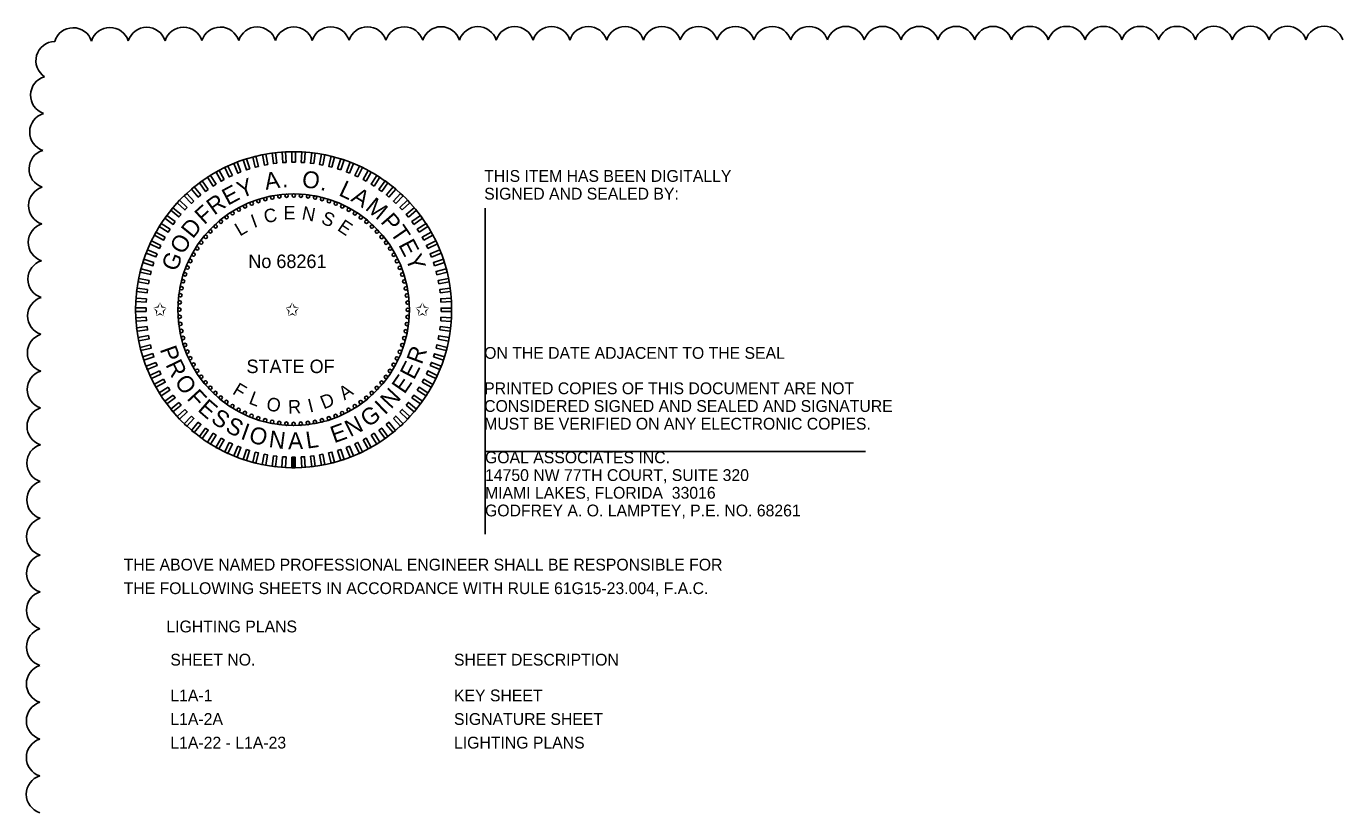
# Model space of a CAD drawing. Extents: x -811.2 to -795.1, y -2238.2 to -2204.
# Drawn here: x -811.08 to -803.27, y -2220.54 to -2215.88 of the extents above; entities that cross this region are included whole.
import ezdxf

# ---------------------------------------------------------------- set-up
doc = ezdxf.new("R2010")
doc.units = 0
for name, color, linetype in [('AdhocPoint_dp', 7, 'Continuous'), ('Cloud_dp', 7, 'Continuous'), ('PlotBorder_dp', 7, 'Continuous'), ('TextMinor', 7, 'Continuous'), ('TextMisc', 7, 'Continuous'), ('TextShtNo', 7, 'Continuous')]:
    doc.layers.add(name, color=color, linetype=linetype)

msp = doc.modelspace()

# ---------------------------------------------------------------- linework, layer by layer
at = {"layer": 'AdhocPoint_dp'}
for p, q in [((-808.3546, -2216.9552), (-808.3546, -2218.8899)), ((-808.3546, -2218.3999), (-806.0979, -2218.3999))]:
    msp.add_line(p, q, dxfattribs=at)
at = {"layer": 'Cloud_dp'}
for centre, radius, start, end in [((-810.7982, -2216.0002), 0.1145, 18.05658, 163.05658), ((-810.58, -2215.9986), 0.1145, 17.79982, 162.79982), ((-810.3617, -2215.9976), 0.1145, 17.71875, 162.71875), ((-810.1434, -2215.9968), 0.1145, 17.67426, 162.67426), ((-809.9251, -2215.9962), 0.1145, 17.64508, 162.64508), ((-809.7068, -2215.9957), 0.1145, 17.62402, 162.62402), ((-809.4885, -2215.9953), 0.1145, 17.60791, 162.60791), ((-809.2702, -2215.9949), 0.1145, 17.59506, 162.59506), ((-809.0518, -2215.9946), 0.1145, 17.5845, 162.5845), ((-808.8335, -2215.9943), 0.1145, 17.57563, 162.57563), ((-808.6152, -2215.994), 0.1145, 17.56803, 162.56803), ((-808.3969, -2215.9937), 0.1145, 17.56143, 162.56143), ((-808.1786, -2215.9935), 0.1145, 17.55563, 162.55563), ((-807.9602, -2215.9933), 0.1145, 17.55047, 162.55047), ((-807.7419, -2215.9931), 0.1145, 17.54585, 162.54585), ((-807.5236, -2215.993), 0.1145, 17.54168, 162.54168), ((-807.3053, -2215.9928), 0.1145, 17.53789, 162.53789), ((-807.087, -2215.9927), 0.1145, 17.53443, 162.53443), ((-806.8686, -2215.9925), 0.1145, 17.53125, 162.53125), ((-806.6503, -2215.9924), 0.1145, 17.52832, 162.52832), ((-806.432, -2215.9923), 0.1145, 17.52559, 162.52559), ((-806.2137, -2215.9922), 0.1145, 17.52306, 162.52306), ((-805.9953, -2215.9922), 0.1145, 17.5207, 162.5207), ((-805.777, -2215.9921), 0.1145, 17.51849, 162.51849), ((-805.5587, -2215.992), 0.1145, 17.51642, 162.51642), ((-805.3404, -2215.992), 0.1145, 17.51447, 162.51447), ((-805.1221, -2215.9919), 0.1145, 17.51263, 162.51263), ((-804.9037, -2215.9919), 0.1145, 17.51089, 162.51089), ((-804.6854, -2215.9918), 0.1145, 17.50924, 162.50924), ((-804.4671, -2215.9918), 0.1145, 17.50767, 162.50767), ((-804.2488, -2215.9918), 0.1145, 17.50619, 162.50619), ((-804.0304, -2215.9917), 0.1145, 17.50477, 162.50477), ((-803.8121, -2215.9917), 0.1145, 17.50342, 162.50342), ((-803.5938, -2215.9917), 0.1145, 17.50213, 162.50213), ((-803.3755, -2215.9917), 0.1145, 17.5009, 162.5009), ((-810.9047, -2216.0812), 0.1144, 91.47713, 236.47713), ((-810.9365, -2216.2866), 0.1145, 105.90805, 250.90805), ((-810.9416, -2216.5046), 0.1145, 106.41676, 251.41676), ((-810.9452, -2216.7227), 0.1145, 106.67623, 251.67623), ((-810.9481, -2216.9409), 0.1145, 106.84098, 251.84098), ((-810.9504, -2217.1592), 0.1145, 106.95758, 251.95758), ((-810.9523, -2217.3774), 0.1145, 107.04572, 252.04572), ((-810.9539, -2217.5957), 0.1145, 107.11538, 252.11538), ((-810.9552, -2217.814), 0.1145, 107.17224, 252.17224), ((-810.9564, -2218.0323), 0.1145, 107.21979, 252.21979), ((-810.9574, -2218.2506), 0.1145, 107.26033, 252.26033), ((-810.9582, -2218.4689), 0.1145, 107.29543, 252.29543), ((-810.9589, -2218.6872), 0.1145, 107.3262, 252.3262), ((-810.9595, -2218.9055), 0.1145, 107.35348, 252.35348), ((-810.9601, -2219.1238), 0.1145, 107.37786, 252.37786), ((-810.9605, -2219.3421), 0.1145, 107.39984, 252.39984), ((-810.9608, -2219.5604), 0.1145, 107.41978, 252.41978), ((-810.9611, -2219.7788), 0.1145, 107.43798, 252.43798), ((-810.9613, -2219.9971), 0.1145, 107.45468, 252.45468), ((-810.9614, -2220.2154), 0.1145, 107.47007, 252.47007), ((-810.9615, -2220.4337), 0.1145, 107.48432, 252.48432)]:
    msp.add_arc(centre, radius, start, end, dxfattribs=at)
at = {"layer": 'TextMinor'}
for radius in [0.9375, 0.6875]:
    msp.add_circle((-809.4901, -2217.5586), radius, dxfattribs=at)
at = {"layer": 'TextShtNo'}
for p, q in [((-809.5001, -2218.4961), (-809.5003, -2218.4336)), ((-809.4901, -2218.4961), (-809.4903, -2218.4336)), ((-809.4801, -2218.4961), (-809.4803, -2218.4336))]:
    msp.add_line(p, q, dxfattribs=at)
for points in [[(-809.8028, -2216.7413), (-809.8215, -2216.7487), (-809.8445, -2216.6906), (-809.8258, -2216.6832)], [(-809.7508, -2216.7232), (-809.77, -2216.7295), (-809.7893, -2216.6701), (-809.7701, -2216.6639)], [(-809.6979, -2216.7085), (-809.7174, -2216.7135), (-809.7329, -2216.6531), (-809.7134, -2216.648)], [(-809.6441, -2216.6971), (-809.6639, -2216.7009), (-809.6756, -2216.6396), (-809.6558, -2216.6358)], [(-809.5897, -2216.6892), (-809.6097, -2216.6917), (-809.6175, -2216.6298), (-809.5975, -2216.6272)], [(-809.5349, -2216.6846), (-809.555, -2216.6859), (-809.559, -2216.6236), (-809.5388, -2216.6223)], [(-809.4799, -2216.6836), (-809.5001, -2216.6836), (-809.5001, -2216.6211), (-809.4799, -2216.6211)], [(-809.425, -2216.6859), (-809.4452, -2216.6847), (-809.4412, -2216.6223), (-809.4211, -2216.6236)], [(-809.3703, -2216.6917), (-809.3904, -2216.6892), (-809.3825, -2216.6273), (-809.3625, -2216.6298)], [(-809.3162, -2216.701), (-809.336, -2216.6972), (-809.3243, -2216.6358), (-809.3045, -2216.6396)], [(-809.2626, -2216.7136), (-809.2822, -2216.7086), (-809.2667, -2216.6481), (-809.2471, -2216.6531)], [(-809.21, -2216.7295), (-809.2292, -2216.7233), (-809.2099, -2216.6639), (-809.1907, -2216.6701)], [(-809.1585, -2216.7488), (-809.1773, -2216.7413), (-809.1543, -2216.6833), (-809.1355, -2216.6907)], [(-809.9504, -2216.8143), (-809.9674, -2216.8251), (-810.0009, -2216.7724), (-809.9838, -2216.7616)], [(-809.9027, -2216.7869), (-809.9204, -2216.7966), (-809.9505, -2216.7419), (-809.9328, -2216.7322)], [(-809.8535, -2216.7625), (-809.8717, -2216.7711), (-809.8983, -2216.7146), (-809.8801, -2216.706)], [(-809.1083, -2216.7712), (-809.1266, -2216.7626), (-809.1, -2216.7061), (-809.0817, -2216.7147)], [(-809.0596, -2216.7967), (-809.0773, -2216.787), (-809.0473, -2216.7323), (-809.0296, -2216.742)], [(-809.0127, -2216.8252), (-809.0297, -2216.8144), (-808.9962, -2216.7617), (-808.9792, -2216.7725)], [(-810.04, -2216.8779), (-810.0556, -2216.8907), (-810.0954, -2216.8426), (-810.0798, -2216.8298)], [(-809.9962, -2216.8447), (-810.0125, -2216.8566), (-810.0492, -2216.806), (-810.0329, -2216.7942)], [(-808.9676, -2216.8567), (-808.9839, -2216.8448), (-808.9472, -2216.7943), (-808.9308, -2216.8061)], [(-808.9245, -2216.8909), (-808.9401, -2216.878), (-808.9003, -2216.8299), (-808.8847, -2216.8427)], [(-810.121, -2216.9522), (-810.1348, -2216.9669), (-810.1804, -2216.9241), (-810.1665, -2216.9094)], [(-810.0817, -2216.9137), (-810.0964, -2216.9276), (-810.1392, -2216.882), (-810.1244, -2216.8682)], [(-808.8837, -2216.9277), (-808.8984, -2216.9139), (-808.8557, -2216.8684), (-808.841, -2216.8822)], [(-808.8453, -2216.967), (-808.8591, -2216.9523), (-808.8136, -2216.9096), (-808.7998, -2216.9243)], [(-810.192, -2217.036), (-810.2039, -2217.0523), (-810.2544, -2217.0156), (-810.2426, -2216.9993)], [(-810.1579, -2216.993), (-810.1707, -2217.0085), (-810.2188, -2216.9687), (-810.206, -2216.9532)], [(-808.8094, -2217.0087), (-808.8223, -2216.9931), (-808.7742, -2216.9533), (-808.7613, -2216.9689)], [(-808.7762, -2217.0525), (-808.7881, -2217.0362), (-808.7376, -2216.9995), (-808.7257, -2217.0158)], [(-810.2235, -2217.0811), (-810.2343, -2217.0982), (-810.287, -2217.0647), (-810.2762, -2217.0477)], [(-808.7459, -2217.0983), (-808.7567, -2217.0813), (-808.7039, -2217.0478), (-808.6931, -2217.0649)], [(-810.2775, -2217.1768), (-810.2861, -2217.1951), (-810.3426, -2217.1685), (-810.334, -2217.1502)], [(-810.252, -2217.1281), (-810.2617, -2217.1458), (-810.3164, -2217.1157), (-810.3067, -2217.098)], [(-808.7184, -2217.146), (-808.7281, -2217.1283), (-808.6734, -2217.0982), (-808.6637, -2217.1159)], [(-808.694, -2217.1952), (-808.7026, -2217.177), (-808.6461, -2217.1504), (-808.6375, -2217.1686)], [(-810.3, -2217.227), (-810.3074, -2217.2458), (-810.3654, -2217.2228), (-810.358, -2217.204)], [(-808.6728, -2217.2459), (-808.6802, -2217.2272), (-808.6222, -2217.2042), (-808.6147, -2217.223)], [(-810.3351, -2217.3311), (-810.3401, -2217.3507), (-810.4006, -2217.3351), (-810.3956, -2217.3156)], [(-810.3192, -2217.2785), (-810.3254, -2217.2977), (-810.3848, -2217.2784), (-810.3786, -2217.2592)], [(-808.6548, -2217.2979), (-808.661, -2217.2787), (-808.6016, -2217.2594), (-808.5954, -2217.2786)], [(-808.64, -2217.3508), (-808.6451, -2217.3313), (-808.5846, -2217.3158), (-808.5796, -2217.3353)], [(-810.3477, -2217.3846), (-810.3515, -2217.4044), (-810.4129, -2217.3927), (-810.4091, -2217.3729)], [(-808.6287, -2217.4046), (-808.6325, -2217.3848), (-808.5711, -2217.3731), (-808.5673, -2217.3929)], [(-810.357, -2217.4388), (-810.3595, -2217.4588), (-810.4215, -2217.451), (-810.4189, -2217.431)], [(-808.6207, -2217.459), (-808.6232, -2217.439), (-808.5613, -2217.4312), (-808.5588, -2217.4512)], [(-810.3652, -2217.5484), (-810.3652, -2217.5686), (-810.4276, -2217.5686), (-810.4276, -2217.5484)], [(-810.3628, -2217.4935), (-810.3641, -2217.5136), (-810.4264, -2217.5097), (-810.4251, -2217.4896)], [(-808.6162, -2217.5138), (-808.6174, -2217.4937), (-808.5551, -2217.4897), (-808.5539, -2217.5099)], [(-808.6151, -2217.5688), (-808.6151, -2217.5486), (-808.5527, -2217.5486), (-808.5527, -2217.5688)], [(-810.3641, -2217.6034), (-810.3628, -2217.6235), (-810.4251, -2217.6274), (-810.4264, -2217.6073)], [(-808.6175, -2217.6237), (-808.6162, -2217.6036), (-808.5539, -2217.6075), (-808.5551, -2217.6276)], [(-810.3595, -2217.6582), (-810.357, -2217.6782), (-810.4189, -2217.686), (-810.4215, -2217.666)], [(-810.3516, -2217.7125), (-810.3478, -2217.7324), (-810.4091, -2217.7441), (-810.4129, -2217.7242)], [(-808.6233, -2217.6784), (-808.6207, -2217.6583), (-808.5588, -2217.6662), (-808.5613, -2217.6862)], [(-810.3402, -2217.7663), (-810.3352, -2217.7859), (-810.3957, -2217.8014), (-810.4007, -2217.7819)], [(-808.6451, -2217.7861), (-808.6401, -2217.7665), (-808.5796, -2217.782), (-808.5846, -2217.8016)], [(-808.6325, -2217.7326), (-808.6287, -2217.7127), (-808.5674, -2217.7244), (-808.5712, -2217.7443)], [(-810.3255, -2217.8193), (-810.3192, -2217.8385), (-810.3786, -2217.8578), (-810.3849, -2217.8386)], [(-808.6611, -2217.8387), (-808.6548, -2217.8195), (-808.5954, -2217.8388), (-808.6017, -2217.858)], [(-810.3075, -2217.8712), (-810.3, -2217.89), (-810.3581, -2217.913), (-810.3655, -2217.8942)], [(-810.2862, -2217.9219), (-810.2776, -2217.9402), (-810.3341, -2217.9668), (-810.3427, -2217.9485)], [(-808.7027, -2217.9404), (-808.6941, -2217.9221), (-808.6376, -2217.9487), (-808.6462, -2217.967)], [(-808.6803, -2217.8902), (-808.6729, -2217.8714), (-808.6148, -2217.8944), (-808.6222, -2217.9132)], [(-810.2618, -2217.9712), (-810.2521, -2217.9889), (-810.3068, -2218.019), (-810.3165, -2218.0013)], [(-810.2344, -2218.0189), (-810.2236, -2218.0359), (-810.2763, -2218.0694), (-810.2871, -2218.0523)], [(-808.7568, -2218.0361), (-808.746, -2218.019), (-808.6932, -2218.0525), (-808.704, -2218.0695)], [(-808.7282, -2217.9891), (-808.7185, -2217.9714), (-808.6638, -2218.0015), (-808.6735, -2218.0191)], [(-810.204, -2218.0647), (-810.1922, -2218.081), (-810.2427, -2218.1177), (-810.2545, -2218.1014)], [(-808.7882, -2218.0812), (-808.7763, -2218.0648), (-808.7258, -2218.1015), (-808.7377, -2218.1179)], [(-810.1708, -2218.1085), (-810.158, -2218.1241), (-810.2061, -2218.1639), (-810.2189, -2218.1483)], [(-810.135, -2218.1502), (-810.1211, -2218.1649), (-810.1667, -2218.2076), (-810.1805, -2218.1929)], [(-808.8592, -2218.165), (-808.8454, -2218.1503), (-808.7999, -2218.193), (-808.8137, -2218.2078)], [(-808.8224, -2218.1242), (-808.8095, -2218.1086), (-808.7614, -2218.1484), (-808.7743, -2218.164)], [(-810.0965, -2218.1895), (-810.0818, -2218.2033), (-810.1246, -2218.2488), (-810.1393, -2218.235)], [(-810.0557, -2218.2263), (-810.0402, -2218.2392), (-810.08, -2218.2873), (-810.0955, -2218.2744)], [(-808.9402, -2218.2393), (-808.9247, -2218.2264), (-808.8848, -2218.2745), (-808.9004, -2218.2874)], [(-808.8985, -2218.2034), (-808.8838, -2218.1896), (-808.8411, -2218.2351), (-808.8558, -2218.2489)], [(-810.0127, -2218.2605), (-809.9964, -2218.2724), (-810.0331, -2218.3229), (-810.0494, -2218.311)], [(-809.9676, -2218.2919), (-809.9505, -2218.3028), (-809.984, -2218.3555), (-810.001, -2218.3447)], [(-809.9206, -2218.3205), (-809.9029, -2218.3302), (-809.933, -2218.3849), (-809.9507, -2218.3752)], [(-809.0775, -2218.3303), (-809.0598, -2218.3206), (-809.0297, -2218.3753), (-809.0474, -2218.385)], [(-809.0299, -2218.3029), (-809.0128, -2218.292), (-808.9794, -2218.3448), (-808.9964, -2218.3556)], [(-808.984, -2218.2725), (-808.9677, -2218.2606), (-808.931, -2218.3111), (-808.9473, -2218.323)], [(-809.8719, -2218.346), (-809.8536, -2218.3546), (-809.8802, -2218.4111), (-809.8985, -2218.4025)], [(-809.8217, -2218.3684), (-809.8029, -2218.3759), (-809.8259, -2218.4339), (-809.8447, -2218.4265)], [(-809.7702, -2218.3876), (-809.751, -2218.3939), (-809.7703, -2218.4533), (-809.7895, -2218.447)], [(-809.7176, -2218.4036), (-809.698, -2218.4086), (-809.7136, -2218.4691), (-809.7331, -2218.4641)], [(-809.2824, -2218.4087), (-809.2628, -2218.4036), (-809.2473, -2218.4641), (-809.2668, -2218.4691)], [(-809.2294, -2218.3939), (-809.2102, -2218.3877), (-809.1909, -2218.4471), (-809.2101, -2218.4533)], [(-809.1775, -2218.3759), (-809.1587, -2218.3685), (-809.1357, -2218.4265), (-809.1545, -2218.434)], [(-809.1268, -2218.3547), (-809.1085, -2218.3461), (-809.0819, -2218.4026), (-809.1002, -2218.4112)], [(-809.6641, -2218.4162), (-809.6443, -2218.42), (-809.656, -2218.4813), (-809.6758, -2218.4775)], [(-809.6099, -2218.4254), (-809.5899, -2218.428), (-809.5977, -2218.4899), (-809.6177, -2218.4874)], [(-809.5552, -2218.4313), (-809.5351, -2218.4325), (-809.539, -2218.4948), (-809.5592, -2218.4936)], [(-809.5003, -2218.4336), (-809.4801, -2218.4336), (-809.4801, -2218.4961), (-809.5003, -2218.4961)], [(-809.4453, -2218.4325), (-809.4252, -2218.4313), (-809.4213, -2218.4936), (-809.4414, -2218.4948)], [(-809.3906, -2218.428), (-809.3705, -2218.4255), (-809.3627, -2218.4874), (-809.3827, -2218.4899)], [(-809.3362, -2218.42), (-809.3163, -2218.4162), (-809.3046, -2218.4776), (-809.3245, -2218.4814)]]:
    msp.add_lwpolyline(points, close=True, dxfattribs=at)
for centre in [(-809.739, -2216.9285), (-809.6989, -2216.9141), (-809.6581, -2216.9023), (-809.6165, -2216.893), (-809.5745, -2216.8864), (-809.5321, -2216.8824), (-809.4896, -2216.8811), (-809.447, -2216.8825), (-809.4047, -2216.8865), (-809.3626, -2216.8932), (-809.3211, -2216.9025), (-809.2802, -2216.9145), (-809.2402, -2216.9289), (-809.8879, -2217.0102), (-809.8527, -2216.9863), (-809.816, -2216.9646), (-809.7781, -2216.9454), (-809.2012, -2216.9458), (-809.1633, -2216.9652), (-809.1266, -2216.9869), (-809.0915, -2217.0108), (-809.9836, -2217.0944), (-809.9535, -2217.0643), (-809.9215, -2217.0362), (-809.0579, -2217.0369), (-809.026, -2217.0651), (-808.9959, -2217.0952), (-810.0379, -2217.1599), (-810.0118, -2217.1263), (-808.9678, -2217.1272), (-808.9417, -2217.1608), (-810.0835, -2217.2317), (-810.0618, -2217.1951), (-808.9178, -2217.1961), (-808.8962, -2217.2327), (-810.1198, -2217.3087), (-810.1029, -2217.2696), (-808.8769, -2217.2706), (-808.86, -2217.3097), (-810.1462, -2217.3896), (-810.1343, -2217.3487), (-808.8456, -2217.3498), (-808.8338, -2217.3907), (-810.1622, -2217.4731), (-810.1555, -2217.4311), (-808.8245, -2217.4322), (-808.8179, -2217.4742), (-810.1676, -2217.558), (-810.1662, -2217.5155), (-808.814, -2217.5166), (-808.8127, -2217.5592), (-810.1663, -2217.6006), (-810.1623, -2217.6429), (-808.8181, -2217.6441), (-808.814, -2217.6017), (-810.1557, -2217.685), (-808.8248, -2217.6861), (-810.1464, -2217.7265), (-810.1346, -2217.7674), (-808.846, -2217.7685), (-808.8341, -2217.7276), (-810.1202, -2217.8075), (-810.1034, -2217.8465), (-808.8774, -2217.8476), (-808.8604, -2217.8085), (-810.0841, -2217.8845), (-810.0624, -2217.9211), (-810.0385, -2217.9563), (-808.9184, -2217.9221), (-808.8967, -2217.8855), (-810.0125, -2217.99), (-809.9844, -2218.0219), (-808.9967, -2218.0228), (-808.9685, -2217.9909), (-808.9424, -2217.9573), (-809.9543, -2218.0521), (-809.9224, -2218.0802), (-809.8888, -2218.1063), (-809.0924, -2218.107), (-809.0587, -2218.0809), (-809.0268, -2218.0528), (-809.8536, -2218.1303), (-809.817, -2218.152), (-809.7791, -2218.1713), (-809.74, -2218.1883), (-809.2413, -2218.1887), (-809.2022, -2218.1718), (-809.1642, -2218.1525), (-809.1276, -2218.1309), (-809.7, -2218.2027), (-809.6591, -2218.2146), (-809.6176, -2218.224), (-809.5756, -2218.2306), (-809.5332, -2218.2347), (-809.4901, -2218.2361), (-809.4481, -2218.2348), (-809.4058, -2218.2308), (-809.3637, -2218.2242), (-809.3222, -2218.2149), (-809.2813, -2218.2031)]:
    msp.add_circle(centre, 0.01, dxfattribs=at)

# ---------------------------------------------------------------- texts
at = {"layer": 'PlotBorder_dp'}
for s, p in [('THIS ITEM HAS BEEN DIGITALLY', (-808.3596, -2216.8)), ('SIGNED AND SEALED BY:', (-808.3596, -2216.905)), ('ON THE DATE ADJACENT TO THE SEAL', (-808.3596, -2217.85)), ('PRINTED COPIES OF THIS DOCUMENT ARE NOT ', (-808.3596, -2218.06)), ('CONSIDERED SIGNED AND SEALED AND SIGNATURE ', (-808.3596, -2218.165)), ('MUST BE VERIFIED ON ANY ELECTRONIC COPIES.', (-808.3596, -2218.27)), ('GOAL ASSOCIATES INC.', (-808.3546, -2218.4699)), ('14750 NW 77TH COURT, SUITE 320', (-808.3546, -2218.5749)), ('MIAMI LAKES, FLORIDA  33016', (-808.3546, -2218.6799)), ('GODFREY A. O. LAMPTEY, P.E. NO. 68261', (-808.3546, -2218.7849)), ('THE ABOVE NAMED PROFESSIONAL ENGINEER SHALL BE RESPONSIBLE FOR ', (-810.4987, -2219.106)), ('THE FOLLOWING SHEETS IN ACCORDANCE WITH RULE 61G15-23.004, F.A.C.', (-810.4987, -2219.246)), ('LIGHTING PLANS', (-810.245, -2219.4731))]:
    msp.add_text(s, height=0.07, dxfattribs=at).set_placement(p)
at = {"layer": 'TextMisc'}
for s, p in [('SHEET NO.', (-810.2215, -2219.67)), ('SHEET DESCRIPTION', (-808.5387, -2219.67)), ('L1A-1', (-810.2215, -2219.8822)), ('KEY SHEET', (-808.5387, -2219.8822)), ('L1A-2A', (-810.2215, -2220.0222)), ('SIGNATURE SHEET', (-808.5387, -2220.0222)), ('L1A-22 - L1A-23', (-810.2215, -2220.1622)), ('LIGHTING PLANS', (-808.5387, -2220.1622))]:
    msp.add_text(s, height=0.07, dxfattribs=at).set_placement(p)
at = {"layer": 'TextShtNo'}
for s, height, rotation, p in [('Y', 0.1, 21.06329, (-809.8021, -2216.8992)), ('A', 0.1, 8.80884, (-809.6551, -2216.848)), ('O', 0.1, 352.18771, (-809.4449, -2216.8305)), ('E', 0.1, 28.10553, (-809.8806, -2216.9424)), ('.', 0.1, 1.04184, (-809.5575, -2216.8322)), ('.', 0.1, 343.52684, (-809.3358, -2216.8456)), ('L', 0.1, 334.67271, (-809.2279, -2216.8778)), ('A', 0.1, 328.40959, (-809.1552, -2216.9105)), ('R', 0.1, 35.92688, (-809.9609, -2217.0013)), ('M', 0.1, 320.6426, (-809.0707, -2216.9617)), ('F', 0.1, 42.37723, (-810.0205, -2217.0577)), ('I', 0.08, 20.01168, (-809.7258, -2217.0745)), ('C', 0.08, 12.20255, (-809.6579, -2217.047)), ('E', 0.08, 0.41861, (-809.5498, -2217.0235)), ('N', 0.08, 349.29143, (-809.4455, -2217.022)), ('S', 0.08, 337.02207, (-809.3325, -2217.0438)), ('P', 0.1, 311.19658, (-808.9784, -2217.0387)), ('D', 0.1, 50.8569, (-810.0886, -2217.1414)), ('L', 0.08, 30.40215, (-809.8093, -2217.125)), ('E', 0.08, 325.86633, (-809.2358, -2217.084)), ('T', 0.1, 304.45632, (-808.9209, -2217.1023)), ('O', 0.1, 59.51777, (-810.1446, -2217.2362)), ('E', 0.1, 297.63152, (-808.8707, -2217.1732)), ('G', 0.1, 68.0518, (-810.1851, -2217.3369)), ('Y', 0.1, 290.58928, (-808.8281, -2217.252)), ('P', 0.1, 289.40551, (-810.2848, -2217.7932)), ('R', 0.1, 69.5134, (-808.7299, -2217.8883)), ('R', 0.1, 296.14576, (-810.2518, -2217.8848)), ('E', 0.1, 62.47116, (-808.7761, -2217.979)), ('E', 0.1, 55.42892, (-808.833, -2218.0634)), ('O', 0.1, 303.96711, (-810.2003, -2217.9854)), ('F', 0.08, 328.72408, (-809.8582, -2218.0552)), ('A', 0.08, 34.49917, (-809.1883, -2218.098)), ('N', 0.1, 47.17876, (-808.9123, -2218.1524)), ('F', 0.1, 312.62798, (-810.1279, -2218.0875)), ('E', 0.1, 319.07833, (-810.0645, -2218.1558)), ('L', 0.08, 339.29159, (-809.7609, -2218.1143)), ('O', 0.08, 349.68206, (-809.6562, -2218.154)), ('R', 0.08, 2.33977, (-809.5217, -2218.1759)), ('I', 0.08, 14.20366, (-809.3941, -2218.1692)), ('D', 0.08, 22.01279, (-809.312, -2218.1505)), ('I', 0.1, 43.64556, (-808.9499, -2218.1869)), ('S', 0.1, 326.12056, (-809.9869, -2218.2217)), ('G', 0.1, 35.11153, (-809.0492, -2218.2601)), ('S', 0.1, 333.193, (-809.9015, -2218.2779)), ('I', 0.1, 340.26543, (-809.8098, -2218.323)), ('O', 0.1, 343.79863, (-809.7621, -2218.3413)), ('E', 0.1, 19.81912, (-809.2498, -2218.3516)), ('N', 0.1, 26.86136, (-809.1544, -2218.3161)), ('N', 0.1, 352.45949, (-809.6411, -2218.3733)), ('A', 0.1, 0.70966, (-809.5227, -2218.3866)), ('L', 0.1, 8.47665, (-809.4105, -2218.3834))]:
    msp.add_text(s, height=height, rotation=rotation, dxfattribs=at).set_placement(p)
for s, p in [('No 68261', (-809.7591, -2217.3114)), ('✩', (-810.3251, -2217.5965)), ('✩', (-809.5404, -2217.5965)), ('✩', (-808.7685, -2217.5965)), ('STATE OF', (-809.7698, -2217.9348))]:
    msp.add_text(s, height=0.08, dxfattribs=at).set_placement(p)

doc.saveas('drawing.dxf')
